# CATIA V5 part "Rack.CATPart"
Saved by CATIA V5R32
Part number: Part2
Bounding box of the stored display mesh (mm): x -50 to 50, y -20 to 20, z 14.357 to 70
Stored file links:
  D:\PROJECTS\Project 2022\CATIA V5 6R 2022\Resources\Part Files\c16_catia_v5_6r2022_prt\Rack Joint(Fig16-57)\Rack.CATPart
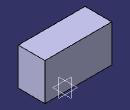
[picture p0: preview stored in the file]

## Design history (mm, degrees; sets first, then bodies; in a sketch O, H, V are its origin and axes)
Body1 (main body)
  Sketch1 on yz-plane, origin (0, 0, 0), H (0, 1, 0), V (0, 0, 1)
    point P1 (20, 30)
    line L1 (-20, 14.3569) -> (20, 14.3569)
    point P2 (-20, 14.3569)
    point P3 (20, 14.3569)
    reference intersected line E1 through (0, 0) direction (-1, 0) from xy-plane
    reference intersected line E3 through (0, 0) direction (0, 1) from zx-plane
    reference intersected line E4 through (0, 0) direction (-1, 0) from xy-plane
    reference intersected line E6 through (0, 0) direction (0, 1) from zx-plane
    line L2 (20, 14.3569) -> (20, 70)
    point P4 (20, 70)
    line L3 (20, 70) -> (-20, 70)
    point P5 (-20, 70)
    line L4 (-20, 14.3569) -> (-20, 70)
    reference intersected line E7 through (0, 0) direction (-1, 0) from xy-plane
    reference intersected line E9 through (0, 0) direction (0, 1) from zx-plane
    distance E1 L1 = 14.3569
    distance P2 E3 = 20
    distance P1 P3 = 15.6431
    distance H L3 = 70
    distance P4 P5 = 40
    horizontal: L1 H, E1 H, E4 H, L3 H, E7 H
    vertical: E3 V, E6 V, L2 V, L4 V, E9 V
    perpendicularity: E7 L2
    coincidence: P1 L2
  Pad1: profile Sketch1, direction (1, 0, 0), length 50, mirrored extent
